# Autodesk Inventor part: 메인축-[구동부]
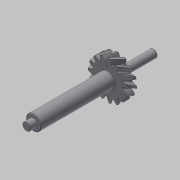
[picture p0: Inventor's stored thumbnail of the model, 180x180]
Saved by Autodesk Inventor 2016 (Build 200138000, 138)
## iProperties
Created: 2016-12
Part Number: 메인축-[구동부]
Material: 강철, 탄소
Document SubType Name: Modeling
Designer: mduedu
Categories: <?xml version="1.0" encoding="UTF-16"?> <MemberInstance><Categories><FamilyTemplate><FamilyTemplateParameter ValueType="xs:double" Id="1" ObjectReferenceKey="da
Density: 7.87 g/cm^3
Mass: 199.41 g
Surface Area: 86.9446 cm^2
Volume: 25.338 cm^3
Appearance: 기본값
CustomPartVersion: 1
Author: mduedu
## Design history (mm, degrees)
sketch "Sketch1"
  geometry: C1 r 19.321 at (0, 0)
  constraints: 1 centre point
  dimensions: "d0" = 38.64102 diameter of C1 (= da_da)
extrude "Extrusion1" new body sketch "Sketch1" distance "d1" = 10 (= da_b); taper "d2" = 0 deg
workplane "Work Plane2"
sketch "Sketch2"
  geometry: C1 r 19.321 at (0, 0) reference; C2 r 17.321 at (0, 0)
  constraints: 1 centre point, 1 coincident
  dimensions: "d3" = 34.64102 diameter of C2 (= da_dw)
feature "피치 지름" sketch "Sketch2" dims "d4" = 10, "d5" = 0
workplane "Work Plane8"
workplane "Work Plane9"
feature "스퍼 기어" dims "da_b" = 10, "da_d" = 34.64102, "da_aw" = 43.87862, "da_da" = 38.64102, "da_df" = 29.64102, "da_dw" = 34.64102, angle "da_beta" = 30 deg, "da_lefttooth" = 0, "da_righttooth" = 10
sketch "스케치3"
  geometry: C1 r 7.5 at (0, 0); 1 further point
  constraints: 1 centre point, 1 coincident
  dimensions: "d49" = 15 diameter of C1
extrude "돌출2" join sketch "스케치3" distance "d50" = 74; taper "d51" = 0 deg
sketch "스케치4"
  geometry: C1 r 4 at (0, 0); 1 further point
  constraints: 1 centre point, 1 coincident
  dimensions: "d52" = 8 diameter of C1
extrude "돌출3" join sketch "스케치4" distance "d53" = 7; taper "d54" = 0 deg
sketch "스케치5"
  geometry: C1 r 7.5 at (0, 0) reference; 1 further point
extrude "돌출4" join sketch "스케치5" distance "d55" = 6; taper "d56" = 0 deg
sketch "스케치6"
  geometry: C1 r 4 at (0, 0); 1 further point
  constraints: 1 centre point, 1 coincident
  dimensions: "d57" = 8 diameter of C1
extrude "돌출5" join sketch "스케치6" distance "d58" = 30; taper "d59" = 0 deg
chamfer "모따기1" distance "d60" = 0.5; stored, may be unused: second distance "d61" = 2, angle "d62" = 45 deg
fillet "모깎기1" dims "d63" = 0.5
sketch "스케치7" dims "d64" = 25
  geometry: C1 r 1 at (0, 12.5); 2 further points
  constraints: 2 vertical alignment, 1 centre point, 1 coincident, 2 other
  dimensions: "d65" = 2 diameter of C1
extrude "돌출6" join sketch "스케치7" distance "d66" = 0.5; taper "d67" = 0 deg
body "Solid1"
body "Srf1"
other parameters: "d16" = 43.87862 (= da_aw), "d17" = 0, "d34" = 12 deg (computed from da_z), "d39" = 0, "d41" = 0, "d43" = 43.87862 (= da_aw), "d46" = 43.87862 (= da_aw), "d47" = 0, "d48" = 0
